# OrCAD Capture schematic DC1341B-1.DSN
size Custom; title: High Efficiency SEPIC Converter; rev: 1; note: DC1341B
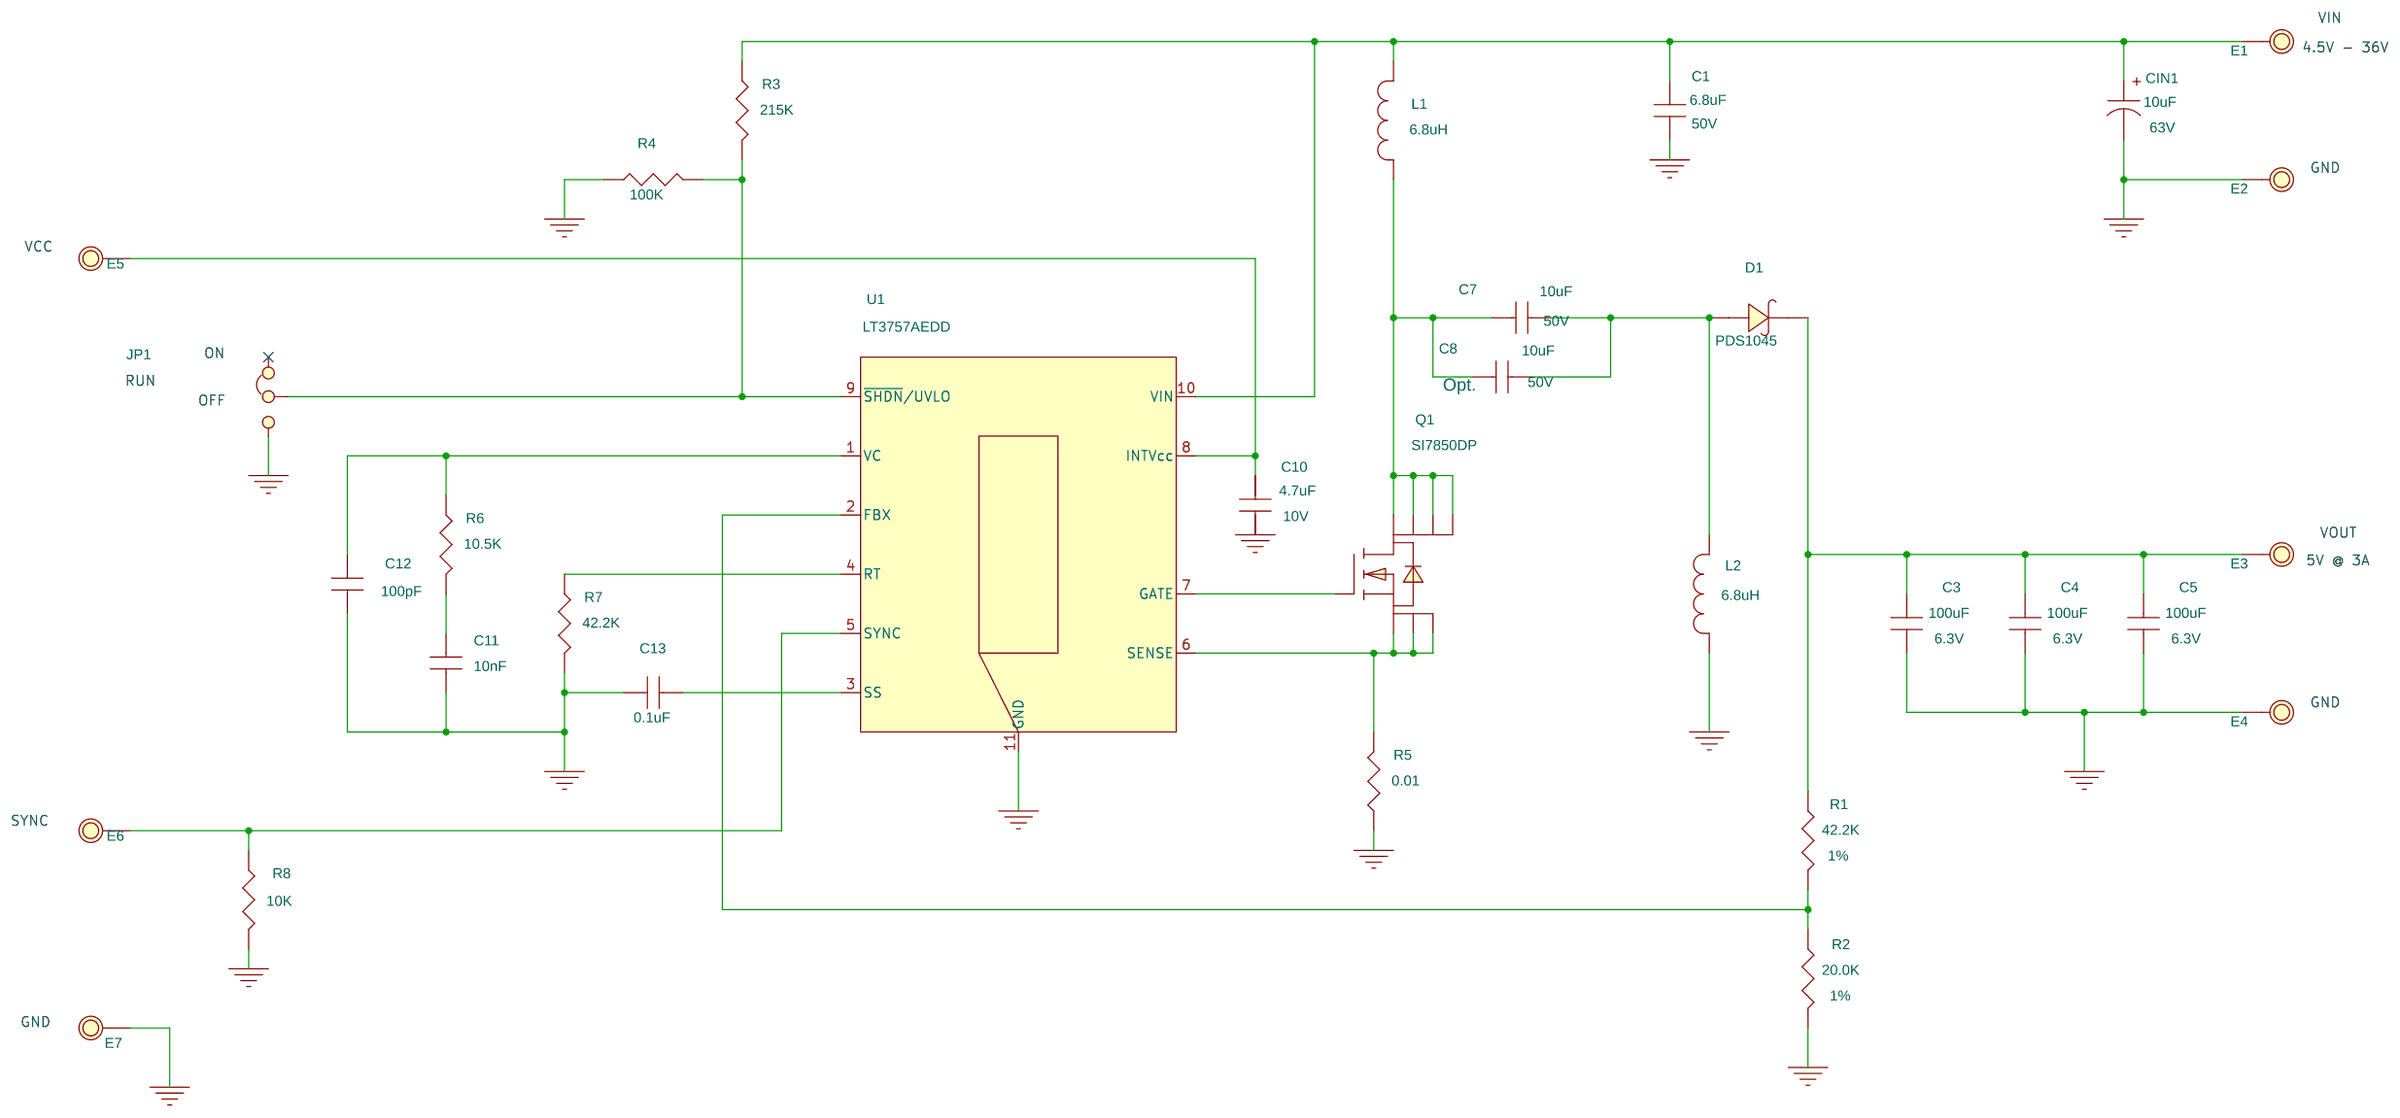
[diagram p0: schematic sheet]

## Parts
C1  6.8uF  [CAP1812]
C3  100uF  [CAP1210]
C4  100uF  [CAP1210]
C5  100uF  [CAP1210]
C7  10uF  [CAP1210]
C8  10uF  [CAP1210]
C10  4.7uF  [CAP0805]
C11  10nF  [CAP0603]
C12  100pF  [CAP0603]
C13  0.1uF  [CAP0603]
CIN1  10uF  [CAP-CE-6.3X5.4]
D1  PDS1045  [POWER-DI-5]
E1  Testpoint  [MM/2501]
E2  Testpoint  [MM/2501]
E3  Testpoint  [MM/2501]
E4  Testpoint  [MM/2501]
E5  Testpoint  [MM/2501]
E6  Testpoint  [MM/2501]
E7  Testpoint  [MM/2501]
JP1  JP3X1/079\NO\12  [JP3X1/079]
L1  6.8uH  [IND-IHLP-4040DZ-11]
L2  6.8uH  [IND-IHLP-4040DZ-11]
Q1  SI7850DP  [POWERPAK-SO-8]
R1  42.2K  [RES0603]
R2  20.0K  [RES0603]
R3  215K  [RES0603]
R4  100K  [RES0603]
R5  0.01  [0815]
R6  10.5K  [RES0603]
R7  42.2K  [RES0603]
R8  10K  [RES0603]
U1  LT3757AEDD  [DFN10]

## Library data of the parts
C1 = CAP1812: 1ST PART FIELD: 50V
C3-C5 = CAP1210: 1ST PART FIELD: 6.3V
C7 = CAP1210: 1ST PART FIELD: 50V
C8 = CAP1210: 1ST PART FIELD: 50V; 3RD PART FIELD: Opt.
C10 = CAP0805: 1ST PART FIELD: 10V
C11-C13 = CAP0402
CIN1 = CAP-CE-6.3X5_0.4: 1ST PART FIELD: 63V; 5TH PART FIELD: 63CE10FS
D1 = PDS1040: 5TH PART FIELD: PDS1045-13
E1-E7 = MillMax-2501
JP1 = JP3X1_079_NO_12
L1 L2 = IND-IHLP-4040DZ-11
Q1 = SI7860DP
R1 R2 = AAC-0402: 2ND PART FIELD: 1%
R3 R6 R7 = AAC-0402
R4 = AAC-0402: 2ND PART FIELD: 1% 0402
R5 = LR-2010: 2ND PART FIELD: 1%, 0815; 4TH PART FIELD: THIN FILM; 5TH PART FIELD: RL3720WTR01F
R8 = AAC-0402: 2ND PART FIELD: 5% 0402
U1 = LT3757EDD_3

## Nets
GND: C1.2 C3.2 C4.2 C5.2 C10.2 C11.2 C12.2 C13.1 CIN1.2 E2.1 E4.1 E7.1 JP1.3 L2.1 R2.2 R4.1 R5.1 R7.2 R8.2 U1.11(GND)
N01031: C7.1 C8.1 L1.1 Q1.5 Q1.6 Q1.7 Q1.8
N01209: Q1.1 Q1.2 Q1.3 R5.2 U1.6(SENSE)
N01269: Q1.4 U1.7(GATE)
N01823: C1.1 CIN1.1 E1.1 L1.2 R3.1 U1.10(VIN)
N01908: C7.2 C8.2 D1.2 L2.2
N02034: R1.2 R2.1 U1.2(FBX)
N02251: C3.1 C4.1 C5.1 D1.1 E3.1 R1.1
N04238: C10.1 E5.1 U1.8(INTVcc)
N04509: JP1.2 R3.2 R4.2 U1.9(~{SHDN}/UVLO)
N06288: C12.1 R6.1 U1.1(VC)
N06338: C11.1 R6.2
N06924: C13.2 U1.3(SS)
N06983: R7.1 U1.4(RT)
N07230: E6.1 R8.1 U1.5(SYNC)

Not connected (* = marked no-connect by the designer): JP1 1*

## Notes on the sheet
- VIN
- 4.5V - 36V
- GND
- VCC
- ON
- RUN
- OFF
- VOUT
- 5V @ 3A
- GND
- SYNC
- GND
